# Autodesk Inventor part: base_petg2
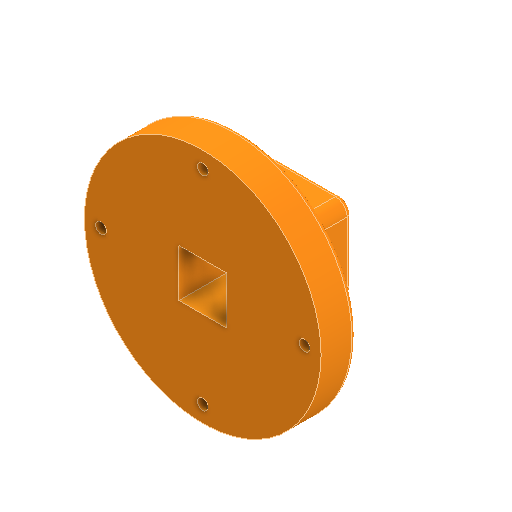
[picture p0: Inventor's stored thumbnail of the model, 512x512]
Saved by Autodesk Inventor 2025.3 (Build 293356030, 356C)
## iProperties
Created: 2025-09
Part Number: base_petg2
Material: Plastica PET
Document SubType Name: Modeling
Designer: Ryzen5700u
Density: 1.541 g/cm^3
Appearance: Arancione
Author: Ryzen5700u
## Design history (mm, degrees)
sketch "Schizzo1"
  geometry: C1 r 50 at (0, 0); 1 further point
  constraints: 1 centre point, 1 coincident
  dimensions: "d0" = 100 diameter of C1
extrude "Estrusione1" new body sketch "Schizzo1" distance "d1" = 15; taper "d2" = 0 deg
sketch "Schizzo2"
  geometry: 2 further points
  dimensions: "d3" = 43 distance of point (0, 0) point (0, 43)
hole "Foro1" sketch "Schizzo2" at (0, 43) diameter "d4" = 4.5; stored, may be unused: countersink angle "d8" = 90 deg, drill point angle "d10" = 118 deg; dims "d5" = 6, "d6" = 8, "d7" = 4.6, "d9" = 8
pattern_circular "Serie circolare1" dims angle "d12" = 360 deg
sketch "Schizzo5"
  geometry: L1 (10.05, 10.05)-(-10.05, 10.05); L2 (-10.05, 10.05)-(-10.05, -10.05); L3 (-10.05, -10.05)-(10.05, -10.05); L4 (10.05, -10.05)-(10.05, 10.05); L5 (10.05, 10.05)-(-10.05, -10.05); L6 (-10.05, 10.05)-(10.05, -10.05); 1 further point
  constraints: 12 end point, 2 midpoint, 2 parallel, 1 horizontal, 1 perpendicular
  dimensions: "d27" = 20.1 distance of L3.end L2.end; "d28" = 20.1 distance of L2.end L1.end
extrude "Estrusione3" cut sketch "Schizzo5" extent not by distance; stored distance "d29" = 0; taper "d30" = 0 deg
sketch "Schizzo8"
  geometry: L1 (10.05, -10.05)-(-10.05, -10.05) reference; L2 (-10.05, -10.05)-(-10.05, 10.05) reference; L3 (-10.05, 10.05)-(10.05, 10.05) reference; L4 (10.05, 10.05)-(10.05, -10.05) reference; L5 (18.05, -18.05)-(-18.05, -18.05); L6 (-18.05, -18.05)-(-18.05, 18.05); L7 (-18.05, 18.05)-(18.05, 18.05); L8 (18.05, 18.05)-(18.05, -18.05); C1 r 4 at (-43, 0) reference; C2 r 4 at (0, -43) reference; C3 r 4 at (43, 0) reference; C4 r 4 at (0, 43) reference; C5 r 50 at (0, 0) reference; 1 further point
  constraints: 8 end point, 3 other
  dimensions: "d35" = 8 distance between parallel lines of L4 L8
extrude "Estrusione5" join sketch "Schizzo8" distance "d36" = 30; taper "d37" = 0 deg
fillet "Raccordo1" dims "d38" = 5
fillet "Raccordo2" dims "d39" = 2
sketch "Schizzo9"
  geometry: L1 (26.1, -23)-(0, -23) reference; L2 (26.1, 0)-(26.1, -23) reference; L3 (0, 0)-(26.1, 0) reference; L4 (0, -23)-(0, 0) reference; L5 (-5, 0)-(0, 0) reference; L6 (26.1, -23)-(0, 0); L7 (0, 0)-(0, -23); L8 (26.1, 0)-(31.1, 0) reference; L9 (26.1, 0)-(0, -23); 2 further points
  constraints: 6 end point, 1 collinear, 1 midpoint
hole "Foro3" sketch "Schizzo9" at (13.05, -11.5) diameter "d40" = 5.5; stored, may be unused: countersink angle "d44" = 90 deg, drill point angle "d46" = 118 deg; dims "d41" = 6, "d42" = 8, "d43" = 4.6, "d45" = 8
sketch "Schizzo10"
  geometry: C1 r 2.75 at (13.05, -11.5) reference; 2 further points
  constraints: 1 coincident
hole "Foro4" sketch "Schizzo10" at (13.05, -11.5) diameter "d48" = 4.5; stored, may be unused: countersink angle "d52" = 90 deg, drill point angle "d54" = 118 deg; dims "d49" = 6, "d50" = 9, "d51" = 3, "d53" = 8
fillet "Raccordo3" dims "d47" = 2
pattern_circular "Serie circolare2" dims "d63" = 360 deg
node "Solido1"
node "Linea chiusa proiettata1"
node "Linea chiusa proiettata2"
